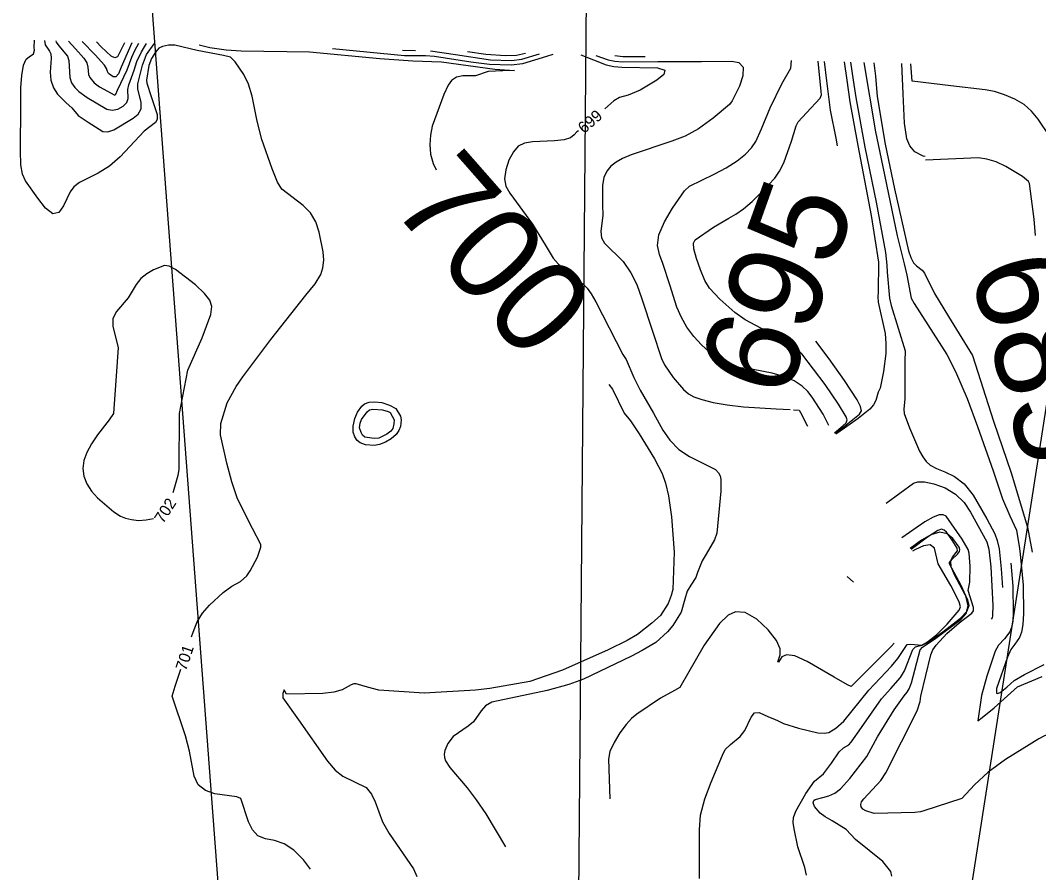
# Model space of a CAD drawing. Extents: x -291892836 to 2945206, y -477993085 to 1832792.
# Drawn here: x 1851267.7 to 1851623.8, y 544938.6 to 545236.7 of the extents above; entities that cross this region are included whole.
import ezdxf

# ---------------------------------------------------------------- set-up
doc = ezdxf.new("R2010")
doc.units = 0
for name, color, linetype in [('DT_X_Contour_Minor', 7, 'Continuous'), ('DT_X_Terrain_Ground_Line', 7, 'Continuous'), ('Level 19', 7, 'Continuous'), ('Level 40', 7, 'Continuous')]:
    doc.layers.add(name, color=color, linetype=linetype)

msp = doc.modelspace()

# ---------------------------------------------------------------- linework, layer by layer
at = {"layer": 'DT_X_Contour_Minor'}
for points in [[(1851327.59, 545021.13), (1851328.12, 545022.73), (1851329.6, 545026.3), (1851331.44, 545029.39), (1851333.84, 545032.23), (1851338.61, 545036.56), (1851341.67, 545038.81), (1851344.72, 545040.51), (1851346.94, 545042.46), (1851348.14, 545044.15), (1851350.62, 545048.94), (1851351.87, 545052.41), (1851351.77, 545053.41), (1851348.85, 545059.02), (1851343.7, 545069.35), (1851341.65, 545075.3), (1851339.93, 545081.86), (1851337.7, 545091.69), (1851337.84, 545095.73), (1851339.99, 545102.99), (1851343.16, 545108.62), (1851345.54, 545112.03), (1851355.33, 545125.12), (1851367.55, 545140.61), (1851370.84, 545144.59), (1851372.79, 545147.83), (1851373.56, 545150.13), (1851373.82, 545152.78), (1851373.62, 545155.75), (1851372.27, 545162.62), (1851371.04, 545166.18), (1851369.2, 545169.38), (1851366.65, 545171.95), (1851359.14, 545177.65), (1851357.64, 545180.09), (1851355.73, 545184.81), (1851352.16, 545195), (1851350.49, 545201.43), (1851348.74, 545210.14), (1851347.49, 545214.37), (1851345.9, 545217.8), (1851342.81, 545222.15), (1851341.21, 545223.77), (1851338.8, 545224.38), (1851329.56, 545226.16), (1851321.8, 545228.01), (1851319.55, 545228.03), (1851317.42, 545227.55), (1851316.14, 545226.96), (1851315.03, 545225.54), (1851313.64, 545223.38), (1851312.71, 545220.88), (1851311.89, 545215.82), (1851311.94, 545214.77), (1851313.48, 545210.06), (1851315.51, 545203.8), (1851315.59, 545201.97), (1851315.02, 545200.95), (1851311.02, 545197.91), (1851305.97, 545192.52), (1851302.61, 545188.95), (1851298.88, 545185.68), (1851294.98, 545183.23), (1851288.35, 545179.97), (1851286.38, 545178.49), (1851285.1, 545176.74), (1851282.79, 545171.77), (1851281.19, 545169.53), (1851279.11, 545169.01), (1851276.53, 545171), (1851273.79, 545174.49), (1851269.57, 545180.57), (1851268.44, 545182.89), (1851267.86, 545186.15), (1851267.72, 545191.1), (1851267.83, 545207.22), (1851267.9, 545213.14), (1851268.19, 545217.39), (1851268.77, 545220.99), (1851269.7, 545223.07), (1851270.76, 545223.98), (1851272.26, 545224.92), (1851272.68, 545226.27), (1851272.56, 545227.21), (1851272.68, 545229.76)], [(1851276.16, 545229.66), (1851276.4, 545228.16), (1851277.4, 545226.55), (1851277.95, 545225.92), (1851278.37, 545224.99), (1851278.52, 545223.49), (1851278.17, 545218.54), (1851278.39, 545215.72), (1851279.31, 545213.12), (1851280.72, 545210.87), (1851283.7, 545207.8), (1851285.77, 545206.09), (1851287.95, 545203.39), (1851291.39, 545201.05), (1851296.59, 545197.82), (1851298.33, 545197.66), (1851300.39, 545198.37), (1851307.2, 545202.49), (1851308.96, 545203.92), (1851309.93, 545205.7), (1851309.93, 545207.99), (1851308.86, 545212.73), (1851308.8, 545214.45), (1851310.41, 545221.07), (1851311.89, 545224.69), (1851314.57, 545228.44), (1851314.75, 545228.55)], [(1851280.09, 545229.55), (1851280.23, 545229.1), (1851281.13, 545227.75), (1851284.17, 545224.2), (1851284.73, 545222.65), (1851284.99, 545216.75), (1851285.66, 545214.88), (1851286.76, 545213.23), (1851288.14, 545211.8), (1851291.11, 545209.68), (1851297.93, 545205.64), (1851299.78, 545205.31), (1851301.81, 545205.68), (1851303.66, 545206.62), (1851304.93, 545207.91), (1851305.37, 545209.35), (1851305.29, 545212.49), (1851305.65, 545214.13), (1851307.55, 545219.29), (1851308.48, 545222.27), (1851310.04, 545225.7), (1851311.81, 545228.64)], [(1851284.56, 545229.42), (1851286.97, 545226.72), (1851289.96, 545223.41), (1851290.94, 545221.82), (1851291.36, 545220.35), (1851291.59, 545217.77), (1851291.99, 545216.66), (1851293.48, 545214.82), (1851295.38, 545213.46), (1851300.76, 545210.48), (1851301.14, 545210.88), (1851301.71, 545212.25), (1851305.11, 545219.4), (1851306.74, 545223.85), (1851307.78, 545226.09), (1851309.2, 545228.71)], [(1851306.67, 545228.79), (1851303, 545220.36), (1851302.01, 545218.01), (1851301.14, 545216.94), (1851300.23, 545216.94), (1851298.54, 545218.11), (1851298.19, 545218.8), (1851297.87, 545219.9), (1851297.15, 545220.99), (1851293.87, 545224.64), (1851289.38, 545229.28)], [(1851304.18, 545228.86), (1851301.69, 545223.88), (1851300.77, 545223.58), (1851299.51, 545224.18), (1851295.99, 545227.47), (1851294.3, 545229.14)], [(1851330.3, 545228.12), (1851333.95, 545227.22), (1851339.75, 545226.33), (1851344.96, 545226.05), (1851368.85, 545225.72), (1851393.4, 545223.32), (1851404.96, 545222.5), (1851415.05, 545222.22), (1851433.7, 545219.63), (1851440.51, 545219.16), (1851436.51, 545219.06), (1851431.3, 545218.82), (1851426.9, 545217.31), (1851422.49, 545217.24), (1851420.26, 545216.8), (1851418.53, 545215.63), (1851417.28, 545213.99), (1851415.82, 545210.8), (1851411.77, 545199.72), (1851411.12, 545196.52), (1851410.89, 545193.22), (1851411.2, 545189.88), (1851412.12, 545186.61), (1851413.1, 545184.38)], [(1851376.85, 545226.88), (1851402.03, 545224.4), (1851409.37, 545224.34), (1851412.57, 545224.18), (1851425.24, 545222.2), (1851431.8, 545221.33), (1851439.4, 545221.1), (1851443.42, 545221.59), (1851451.9, 545224.15), (1851454.06, 545224.83)], [(1851401.34, 545226.23), (1851405.92, 545226.11)], [(1851411.17, 545225.97), (1851419.87, 545224.71), (1851432.19, 545222.92), (1851439.45, 545222.68), (1851443.13, 545223.13), (1851449.31, 545224.96)], [(1851444.42, 545225.09), (1851441.24, 545224.37), (1851437.34, 545224.26), (1851430.52, 545224.71), (1851424.15, 545225.63)], [(1851463.75, 545224.57), (1851472.57, 545221.18), (1851475.24, 545220.58), (1851478.06, 545220.33), (1851490.54, 545220.09), (1851493.09, 545219.29), (1851492.75, 545217.73), (1851490.36, 545215.74), (1851484.45, 545212.28), (1851480.32, 545210.58), (1851477.2, 545209.67), (1851475.23, 545208.49), (1851472.09, 545205.76)], [(1851469.02, 545224.43), (1851473.25, 545222.91), (1851475.68, 545222.36), (1851478.27, 545222.13), (1851490.63, 545222.26), (1851505.96, 545222.35), (1851516.54, 545222.42), (1851518.99, 545221.93), (1851520.52, 545220.33), (1851520.44, 545217.33), (1851519.26, 545213.69), (1851516.69, 545208.51), (1851515.7, 545207.3), (1851510.05, 545202.49), (1851504.93, 545198.78), (1851500.21, 545196.21), (1851495.56, 545194.44), (1851481.29, 545189.63), (1851478.33, 545188.39), (1851476.06, 545187.13), (1851474.28, 545185.7), (1851472.85, 545183.95), (1851471.81, 545181.76), (1851471.26, 545179.02), (1851471.36, 545172.11), (1851471.39, 545168.6), (1851470.77, 545162.85), (1851470.98, 545160.63), (1851472.03, 545158.8), (1851478.58, 545152.35), (1851481.23, 545148.35), (1851483.32, 545144.31), (1851485.12, 545139.35), (1851488.83, 545128.04), (1851491.95, 545118.48), (1851493.02, 545116.24), (1851495.98, 545111.81), (1851499.64, 545107.6), (1851501.34, 545106.12), (1851503.31, 545105.01), (1851506.08, 545104.05), (1851510.01, 545103.09), (1851514.95, 545102.21), (1851520.58, 545101.51), (1851531.99, 545100.83), (1851536.92, 545100.57)], [(1851486.19, 545223.98), (1851478.44, 545223.93), (1851475.57, 545224.26)], [(1851550.5, 545095.01), (1851548.46, 545098.95), (1851544.61, 545104.87), (1851543.08, 545106.86), (1851541.1, 545108.8), (1851538.35, 545110.57), (1851534.66, 545112.09), (1851530.59, 545113.29), (1851523.99, 545114.6), (1851517.01, 545115.58), (1851515.27, 545116.26), (1851513.3, 545117.32), (1851511.06, 545118.82), (1851508.57, 545120.79), (1851505.88, 545123.26), (1851503.2, 545126.15), (1851500.81, 545129.35), (1851498.89, 545132.79), (1851497.34, 545136.43), (1851494.81, 545144.21), (1851492.39, 545151.66), (1851491.2, 545154.81), (1851490.55, 545157.96), (1851491.03, 545161.68), (1851492.99, 545166.25), (1851495.74, 545170.96), (1851499.99, 545177.09), (1851501.76, 545178.65), (1851510.41, 545182.88), (1851514.54, 545185.14), (1851518.4, 545187.56), (1851521.35, 545189.92), (1851523.44, 545192.16), (1851524.88, 545194.27), (1851526.88, 545198.71), (1851530, 545206.07), (1851534.06, 545214.44), (1851537.15, 545220), (1851537.46, 545222.62)], [(1851552.47, 545092.49), (1851555.4, 545094.84), (1851556.48, 545095.98), (1851556.89, 545096.95), (1851556.58, 545098.08), (1851553.87, 545102.42), (1851549.19, 545109.29), (1851541.08, 545120.09), (1851539.41, 545121.83), (1851536.32, 545123.87), (1851521.17, 545131.91), (1851517.62, 545134.49), (1851512.36, 545139.24), (1851508.73, 545143.07), (1851507.13, 545145.72), (1851505.54, 545149.4), (1851504.17, 545153.39), (1851503.28, 545156.74), (1851503.12, 545158.76), (1851503.75, 545159.92), (1851510.1, 545164.31), (1851515.44, 545167.49), (1851517.94, 545168.92), (1851520.63, 545170.78), (1851523.63, 545173.35), (1851529.42, 545179.13), (1851531.58, 545181.55), (1851533.27, 545183.94), (1851534.74, 545186.84), (1851537.4, 545194.49), (1851539.06, 545199.83), (1851539.75, 545201.14), (1851542.67, 545204.32), (1851547.45, 545209.53), (1851547.88, 545210.61), (1851547.81, 545211.82), (1851546.69, 545222.37)], [(1851553.45, 545192.76), (1851553.05, 545195.47), (1851551.1, 545205.28), (1851549.78, 545215.51), (1851549, 545222.31)], [(1851555.85, 545222.13), (1851556.71, 545215.73), (1851557.79, 545208.14), (1851560.6, 545192.94), (1851565.25, 545168.44), (1851567.83, 545152.08), (1851567.73, 545141.62), (1851567.62, 545140.05), (1851567.75, 545138.17), (1851570.15, 545127.23), (1851570.41, 545123.74), (1851570.38, 545120.22), (1851569.6, 545113.89), (1851568.42, 545108.12), (1851567.74, 545106.63), (1851566.95, 545103.79), (1851566.12, 545102.18), (1851564.84, 545100.7), (1851560.67, 545097.48), (1851555.91, 545094.04), (1851552.91, 545091.92)], [(1851558.1, 545222.07), (1851559.03, 545215.81), (1851559.92, 545209.73), (1851563.08, 545192.33), (1851567, 545173.12), (1851570.27, 545155.45), (1851570.78, 545151.09), (1851570.84, 545148.65), (1851571.67, 545139.52), (1851572.24, 545136.96), (1851577.21, 545121.16), (1851577.03, 545117.51), (1851577.03, 545111.6), (1851577.04, 545104.3), (1851576.66, 545100.75), (1851576.83, 545099.23), (1851578.63, 545094.22), (1851582.18, 545086.06), (1851583.29, 545084), (1851584.47, 545082.4), (1851585.96, 545081.12), (1851588.07, 545080.01), (1851590.98, 545078.84), (1851594.37, 545077.19), (1851597.8, 545074.56), (1851600.91, 545070.7), (1851605.71, 545062.34), (1851608.5, 545057.18), (1851609.35, 545054.82), (1851609.98, 545051.84), (1851610.78, 545044.89), (1851611.15, 545038.33)], [(1851562.69, 545221.95), (1851566.84, 545197.65), (1851568.78, 545188.27), (1851574.4, 545161.31), (1851576.79, 545151.5), (1851577.79, 545147.53), (1851579.3, 545139.59), (1851580.31, 545137.63), (1851591.77, 545119.88), (1851594.8, 545113.94), (1851598.85, 545104.47), (1851602.49, 545094.61), (1851607.95, 545079.13), (1851611.18, 545069.37), (1851613.77, 545063.47), (1851616.14, 545058.37), (1851617.15, 545051.98), (1851617.35, 545050.05)], [(1851566.16, 545221.85), (1851566.82, 545217.12), (1851567.42, 545210.09), (1851570.2, 545193.39), (1851573.44, 545177.71), (1851578.28, 545156.09), (1851579.12, 545153.73), (1851580.07, 545151.94), (1851581.13, 545150.81), (1851583.15, 545149.3), (1851583.92, 545148.25), (1851587.44, 545141.19), (1851592.33, 545133.16), (1851600.73, 545119.47), (1851608.03, 545096.55), (1851614.26, 545078.44), (1851619.94, 545059.43), (1851621.57, 545050.69)], [(1851584.18, 545189.05), (1851583.5, 545189.21), (1851580.57, 545190.7), (1851578.74, 545192.86), (1851577.8, 545195.3), (1851576.92, 545200.78), (1851576.5, 545211), (1851576, 545221.59)], [(1851631.82, 545190.04), (1851623.66, 545202.15), (1851621.4, 545204.94), (1851618.79, 545207.21), (1851615.52, 545209.12), (1851611.89, 545210.65), (1851608.36, 545211.75), (1851605.19, 545212.42), (1851593.15, 545213.74), (1851579.63, 545215.45), (1851579.19, 545221.51)], [(1851462.9, 545198.05), (1851462.39, 545197.65), (1851461.4, 545196.62), (1851460.08, 545195.63), (1851457.9, 545194.89), (1851454.54, 545194.55), (1851446.86, 545194.24), (1851444, 545193.74), (1851441.87, 545192.66), (1851440.14, 545190.72), (1851438.61, 545187.82), (1851437.48, 545184.45), (1851437.03, 545181.27), (1851437.51, 545178.7), (1851438.89, 545176.31), (1851446.85, 545165.41), (1851451.28, 545158.2), (1851454.03, 545153.51), (1851455.75, 545151.54), (1851459.68, 545148.18), (1851464.56, 545144.43), (1851465.96, 545142.99), (1851467.4, 545141.03), (1851469.03, 545138.24), (1851478.47, 545119.82), (1851479.61, 545118.03), (1851482.24, 545111.81), (1851484.51, 545107.33), (1851489.19, 545099.28), (1851492.39, 545093.41), (1851494.85, 545089.9), (1851497.98, 545086.66), (1851501.74, 545084.12), (1851510.79, 545079.57), (1851511.89, 545078.51), (1851512.41, 545077.41), (1851512.67, 545076.09), (1851512.64, 545072.05), (1851511.26, 545057.35), (1851510.49, 545055), (1851507.55, 545050.03), (1851506.13, 545047.63), (1851504.56, 545043.55), (1851503.95, 545041.87), (1851502.23, 545039.14), (1851500.94, 545037.07), (1851500.16, 545034.32), (1851498.79, 545029.76), (1851495.86, 545025.06), (1851494.02, 545022.8), (1851490, 545019.12), (1851485.24, 545016.33), (1851481.49, 545014.39), (1851464.61, 545006.36), (1851459.56, 545004.49), (1851451.91, 545002.38), (1851432.66, 544998.27), (1851430.45, 544997.02), (1851428.83, 544995.28), (1851426.16, 544991.4), (1851424.38, 544989.82), (1851419.14, 544986.21), (1851417.23, 544983.84), (1851416.14, 544981.34), (1851415.94, 544980.1), (1851416.02, 544978.91), (1851416.38, 544977.76), (1851417.91, 544975.47), (1851423.94, 544968.36), (1851427.14, 544964.16), (1851430.5, 544959.25), (1851437.43, 544947.72)], [(1851622.77, 545161.43), (1851622.3, 545167.11), (1851620.59, 545179.64), (1851620.25, 545180.38), (1851618.15, 545182.05), (1851612.35, 545185.62), (1851608.93, 545187.23), (1851605.75, 545188.19), (1851602.81, 545188.56), (1851584.23, 545187.78)], [(1851321.14, 545071.55), (1851321.27, 545071.87), (1851322.95, 545077.65), (1851323.23, 545079.64), (1851323.43, 545099.16), (1851326.28, 545114.33), (1851331.28, 545125.66), (1851334.31, 545133.79), (1851334.71, 545136.61), (1851334.03, 545138.85), (1851332.1, 545141.21), (1851328.93, 545144.14), (1851321.97, 545149.53), (1851319.73, 545150.73), (1851318.13, 545150.9), (1851314.34, 545149.41), (1851311.96, 545148.07), (1851309.83, 545146.36), (1851308.26, 545144.27), (1851305.39, 545139.6), (1851301.35, 545134.93), (1851300.09, 545132.39), (1851300.07, 545129.6), (1851301.95, 545122.34), (1851301.61, 545117.28), (1851300.35, 545099.18), (1851298.73, 545097.03), (1851294.69, 545091.77), (1851292.58, 545088.62), (1851290.97, 545085.62), (1851289.96, 545082.77), (1851289.62, 545080.01), (1851289.97, 545077.26), (1851290.98, 545074.59), (1851292.6, 545072.03), (1851294.71, 545069.68), (1851300.36, 545064.81), (1851302.74, 545063.3), (1851304.45, 545062.64), (1851306.6, 545062.1), (1851309.08, 545061.84), (1851311.74, 545061.98), (1851314.23, 545062.52)], [(1851552.55, 545092.39), (1851555.94, 545094.81), (1851561.21, 545098.97), (1851561.9, 545100.18), (1851561.58, 545101.65), (1851560.33, 545103.97), (1851555.94, 545110.79), (1851550.58, 545118.3), (1851545.88, 545124.52)], [(1851473.55, 545109.35), (1851474.83, 545107.68), (1851478.91, 545099.29), (1851481.13, 545096.59), (1851484.15, 545092.12), (1851489.49, 545083.33), (1851492.14, 545078.21), (1851493.33, 545074.83), (1851494.36, 545070.43), (1851495.47, 545063.11), (1851496.33, 545050.66), (1851495.88, 545037.71), (1851495.37, 545035.52), (1851494.26, 545032.74), (1851491.56, 545028.55), (1851488.55, 545025.83), (1851483.5, 545021.88), (1851479.9, 545019.84), (1851473.26, 545016.58), (1851457.33, 545009.48), (1851445.87, 545005.5), (1851431.94, 545003.08), (1851426.95, 545002.4), (1851408.9, 545001.36), (1851393.11, 545002.44), (1851389.17, 545003.45), (1851385.12, 545004.7), (1851384.38, 545004.66), (1851383.42, 545004.3), (1851380.25, 545002.55), (1851377.4, 545001.74), (1851373.46, 545001.32), (1851360.8, 545001.06), (1851359.97, 545002.59), (1851359.46, 545001.33), (1851359.53, 544999.82), (1851364.94, 544992.05), (1851375.13, 544977.6), (1851377.82, 544974.51), (1851380.49, 544972.36), (1851388.68, 544968.38), (1851390.49, 544966.14), (1851391.77, 544963.44), (1851394.33, 544956.47), (1851396.7, 544952.35), (1851405.21, 544939.93), (1851406.41, 544937.25)], [(1851399.02, 545100.99), (1851400.7, 545098.32), (1851400.93, 545097.02), (1851400.62, 545094.62), (1851400.07, 545093.25), (1851399.16, 545091.84), (1851397.46, 545090.32), (1851395.42, 545089.15), (1851393.33, 545088.32), (1851391.52, 545088), (1851388.37, 545088.29), (1851386.55, 545088.93), (1851385.48, 545089.73), (1851384.64, 545091.02), (1851384.14, 545092.69), (1851384.14, 545094.83), (1851384.68, 545097.41), (1851385.67, 545099.67), (1851387.17, 545101.71), (1851388.13, 545102.54), (1851389.73, 545103.11), (1851391.74, 545103.28), (1851394.17, 545103.01), (1851396.77, 545102.11), (1851399.02, 545100.99)], [(1851397.01, 545099.51), (1851398.49, 545097.03), (1851398.38, 545095.59), (1851398.04, 545094), (1851397.33, 545093), (1851395.9, 545092.03), (1851393.05, 545090.6), (1851391.51, 545090.51), (1851388.25, 545090.94), (1851387.37, 545091.58), (1851386.91, 545092.53), (1851386.37, 545094.23), (1851386.51, 545095.83), (1851387, 545097.07), (1851388.98, 545099.76), (1851389.84, 545100.5), (1851391.03, 545100.74), (1851394.36, 545100.48), (1851396.33, 545099.87), (1851397.01, 545099.51)], [(1851538.12, 545100.51), (1851540.06, 545100.4), (1851540.59, 545099.59), (1851543.04, 545094.77)], [(1851570.54, 545067.81), (1851580.11, 545074.86), (1851581.62, 545075.35), (1851583.89, 545075.33), (1851587.23, 545074.66), (1851591.12, 545073.26), (1851594.81, 545071.04), (1851597.75, 545068.03), (1851600.01, 545064.66), (1851605.71, 545054.28), (1851606.39, 545051.77), (1851607.11, 545045.58), (1851607.8, 545032.05), (1851607.74, 545028.73), (1851607.69, 545028.5)], [(1851583.66, 544960.25), (1851582.57, 544959.89), (1851580.53, 544959.63), (1851566.27, 544959.28), (1851563.35, 544960.22), (1851562.4, 544960.87), (1851561.79, 544961.63), (1851561.6, 544962.47), (1851561.89, 544963.41), (1851562.65, 544964.46), (1851568.7, 544970.81), (1851570.35, 544973.53), (1851581.4, 544995.27), (1851582.36, 544998.49), (1851582.67, 545000.39), (1851586.09, 545014.85), (1851586.85, 545016.61), (1851587.98, 545018.24), (1851591.77, 545022.26), (1851596.03, 545026.01), (1851600.42, 545029.37), (1851601.02, 545030.21), (1851601.06, 545031.31), (1851599.24, 545037.35), (1851599.81, 545040.27), (1851599.84, 545045.84), (1851599.56, 545050.31), (1851599.21, 545051.68), (1851597.12, 545055.24), (1851591.47, 545063.27), (1851590.48, 545063.77), (1851589.05, 545063.78), (1851586.95, 545063.01), (1851584.09, 545061.33), (1851576.01, 545055.74)], [(1851542.68, 544937.75), (1851542.1, 544940.4), (1851539.68, 544947.63), (1851538.3, 544954), (1851538, 544956.15), (1851538.15, 544957.94), (1851538.96, 544960.09), (1851542.37, 544966.32), (1851545.49, 544970.6), (1851548.55, 544973.24), (1851551.43, 544976.98), (1851554.13, 544980.86), (1851555.62, 544982.28), (1851557.47, 544983.38), (1851558.33, 544984.32), (1851561.94, 544989.45), (1851568.93, 544999.46), (1851572.14, 545003.07), (1851575.5, 545006.85), (1851576.97, 545009.24), (1851579.79, 545016.63), (1851580.74, 545017.58), (1851583.37, 545018.32), (1851585.22, 545019.27), (1851590.31, 545022.81), (1851596.57, 545027.68), (1851598.75, 545030.02), (1851599.53, 545032.04), (1851599.1, 545034.03), (1851594.38, 545042.74), (1851593.28, 545045.62), (1851593.16, 545047.65), (1851593.73, 545048.96), (1851595.49, 545051.14), (1851595.33, 545052.07), (1851593.63, 545054.94), (1851591.64, 545057.66), (1851590.78, 545058.46), (1851589.83, 545058.71), (1851588.62, 545058.34), (1851585.02, 545055.93), (1851579.22, 545051.64)], [(1851572.49, 544937.45), (1851572.16, 544939), (1851569.39, 544942.59), (1851559.84, 544950.28), (1851556.55, 544953.76), (1851551.6, 544956.74), (1851549.18, 544958.14), (1851547.39, 544959.49), (1851545.49, 544961.74), (1851544.99, 544963.04), (1851545.18, 544963.83), (1851545.64, 544964.18), (1851548.31, 544964.89), (1851550.41, 544965.48), (1851552.6, 544966.46), (1851554.58, 544967.97), (1851557.77, 544971.55), (1851563.78, 544979.29), (1851567.53, 544986.17), (1851573.35, 544995.6), (1851576.76, 545000.45), (1851577.91, 545001.72), (1851578.58, 545002.88), (1851579.34, 545004.99), (1851582.35, 545016.56), (1851583.21, 545017.47), (1851587.4, 545020.29), (1851596.67, 545027.13), (1851598.54, 545029.31), (1851599.16, 545031.98), (1851598.37, 545035.4), (1851596.73, 545039.06), (1851592.68, 545046.62), (1851592.67, 545047.15), (1851593.58, 545048.22), (1851595.43, 545050.02), (1851596.12, 545050.93), (1851596.33, 545051.68), (1851596, 545052.51), (1851593.79, 545055.48), (1851591.85, 545057.08), (1851589.28, 545057.7), (1851586.12, 545056.78), (1851582.85, 545054.89), (1851578.94, 545052)], [(1851505.18, 544936.56), (1851505.28, 544943.02), (1851505.19, 544953.66), (1851505.6, 544958.7), (1851507.15, 544964.4), (1851509.35, 544970.33), (1851513.3, 544979.71), (1851514.2, 544981.7), (1851516.04, 544983.51), (1851519.43, 544986.28), (1851521.05, 544988.3), (1851523.26, 544993.05), (1851524.47, 544994.51), (1851526.11, 544994.66), (1851529.36, 544993.12), (1851530.92, 544992.57), (1851532.52, 544991.89), (1851534.63, 544990.85), (1851539.86, 544989.13), (1851546.59, 544987.58), (1851548.86, 544987.43), (1851550.42, 544987.71), (1851552.96, 544989.16), (1851555.69, 544991.67), (1851564.43, 545002.44), (1851572.43, 545010.82), (1851574.6, 545013.48), (1851577.83, 545018.38), (1851579.12, 545018.6), (1851582.97, 545018.19), (1851584.93, 545019.33), (1851588.11, 545021.79), (1851591.9, 545025.49), (1851596.09, 545030.4), (1851596.47, 545031.58), (1851596.05, 545033.33), (1851593.12, 545039.1), (1851588.71, 545046.66), (1851587.37, 545052.13), (1851585.93, 545053.26), (1851583.53, 545052.93), (1851580.77, 545051.68), (1851579.7, 545051.04)], [(1851617.35, 545050.05), (1851618.47, 545039.13), (1851618.55, 545029.27), (1851618.32, 545025.47), (1851617.82, 545022.69), (1851617.13, 545020.82), (1851615.56, 545018.54), (1851614.15, 545016.65), (1851613, 545014.04), (1851609.16, 545003.01), (1851609.09, 545001.45), (1851609.5, 545001.25), (1851610.34, 545001.63), (1851612.73, 545003.54), (1851615.33, 545005.81), (1851618.89, 545007.97), (1851625.78, 545011.42)], [(1851614.15, 545046.85), (1851614.83, 545038.78), (1851614.97, 545029.55), (1851614.79, 545026.55), (1851614.39, 545024.37), (1851613.76, 545022.83), (1851611.85, 545020.41), (1851609.83, 545018.14), (1851608.68, 545016.05), (1851605.69, 545007.34), (1851603.9, 545000.57), (1851602.55, 544991.71), (1851604.05, 544992.94), (1851608.29, 544996.29), (1851616.41, 545003.59), (1851625.13, 545007.27)], [(1851556.88, 545042.26), (1851559.04, 545040.21)], [(1851573.26, 545018.87), (1851572.23, 545017.73), (1851558.26, 545003.77), (1851556.98, 545004.35), (1851552.33, 545006.99), (1851542.93, 545012.46), (1851538.56, 545014.42), (1851535.67, 545014.82), (1851534.06, 545014.12), (1851532.82, 545012.23), (1851532.67, 545012.39), (1851533.44, 545014.79), (1851533.43, 545016.87), (1851532.19, 545019.82), (1851529.27, 545023.6), (1851525.3, 545027.26), (1851521.23, 545029.63), (1851517.82, 545029.88), (1851515.21, 545028.68), (1851512.27, 545025.77), (1851506.88, 545018.21), (1851498.36, 545003.4), (1851496.52, 545002.36), (1851491.58, 544999.64), (1851483.34, 544994.06), (1851481.51, 544992.53), (1851479.54, 544990.43), (1851477.37, 544987.52), (1851475.35, 544984.2), (1851473.92, 544981), (1851473.4, 544978.3), (1851473.82, 544964.41)], [(1851607.69, 545028.5), (1851607.53, 545027.74), (1851607.25, 545027.25)], [(1851369.21, 544939.84), (1851366.8, 544943.07), (1851363.41, 544946.49), (1851359.99, 544948.74), (1851356.6, 544949.85), (1851353.46, 544950.51), (1851350.82, 544951.57), (1851348.88, 544953.65), (1851347.54, 544956.4), (1851344.77, 544964.61), (1851343.45, 544965.18), (1851335.69, 544966.26), (1851332.45, 544967.42), (1851329.9, 544969.41), (1851328.49, 544972.39), (1851326.92, 544981.11), (1851325.49, 544986.51), (1851320.83, 545000.37), (1851321.87, 545003.88), (1851323.81, 545009.75)], [(1851691.56, 544978.75), (1851673.46, 544987.33), (1851670.38, 544988.42), (1851667.03, 544989.26), (1851663.24, 544989.72), (1851658.97, 544989.76), (1851636.84, 544988.63), (1851628.61, 544987.26), (1851625.9, 544986.45), (1851623.85, 544985.45), (1851612.28, 544978.17), (1851606.21, 544973.82), (1851601.37, 544969.41), (1851597.01, 544964.62), (1851583.66, 544960.25)]]:
    msp.add_lwpolyline(points, dxfattribs=at)
at = {"layer": 'Level 40'}
for p, q in [((1851666.59, 545359.82), (1851524.12, 544444.79)), ((1851304.99, 545356.29), (1851371.4, 544477.62)), ((1851466.42, 545337.49), (1851458.89, 544451.45))]:
    msp.add_line(p, q, dxfattribs=at)

# ---------------------------------------------------------------- texts
at = {"layer": 'DT_X_Terrain_Ground_Line'}
for s, rotation, p in [('700', 311.2765, (1851396.65, 545171.83)), ('695', 70.3617, (1851535.29, 545103.21)), ('685', 285.6013, (1851599.45, 545150.08))]:
    msp.add_text(s, height=33, rotation=rotation, dxfattribs=at).set_placement(p)
at = {"layer": 'Level 19'}
for s, rotation, p in [('699', 40.5883, (1851464.85, 545196.91)), ('702', 57.3187, (1851317.65, 545060.45)), ('701', 71.6484, (1851325.67, 545008.98))]:
    msp.add_text(s, height=4, rotation=rotation, dxfattribs=at).set_placement(p)

doc.saveas('drawing.dxf')
